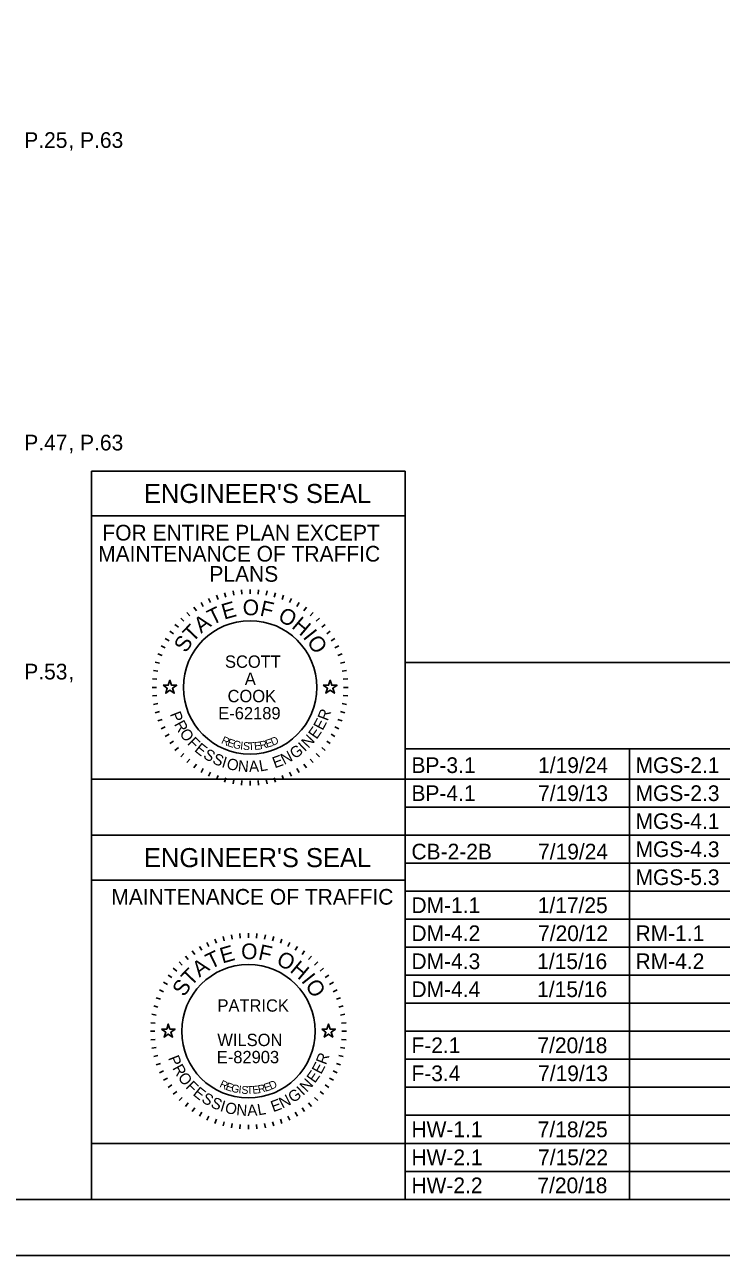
# Model space of a CAD drawing. Extents: x 0 to 34, y -32.5 to 22.
# Drawn here: x 6.75 to 12.97, y 0 to 10.98 of the extents above; entities that cross this region are included whole.
import ezdxf

# ---------------------------------------------------------------- set-up
doc = ezdxf.new("R2010")
doc.units = 0
for name, color, linetype in [('Default', 7, 'Continuous'), ('GM_X_Adjacent_County', 7, 'Continuous'), ('GM_X_County', 7, 'Continuous'), ('GM_X_Section', 7, 'Continuous'), ('GM_X_Township', 7, 'Continuous')]:
    doc.layers.add(name, color=color, linetype=linetype)

msp = doc.modelspace()

# ---------------------------------------------------------------- linework, layer by layer
at = {"layer": 'Default'}
for points in [[(7.988, 5.089), (8.035, 5.089), (8.05, 5.133), (8.064, 5.089), (8.111, 5.089), (8.073, 5.061), (8.088, 5.017), (8.05, 5.044), (8.012, 5.017), (8.026, 5.061)], [(9.418, 5.089), (9.465, 5.089), (9.48, 5.133), (9.494, 5.089), (9.541, 5.089), (9.503, 5.061), (9.518, 5.017), (9.48, 5.044), (9.442, 5.017), (9.456, 5.061)], [(7.974, 2.02), (8.021, 2.02), (8.035, 2.065), (8.049, 2.02), (8.096, 2.02), (8.058, 1.992), (8.073, 1.948), (8.035, 1.975), (7.997, 1.948), (8.012, 1.992)], [(9.404, 2.02), (9.451, 2.02), (9.465, 2.065), (9.479, 2.02), (9.526, 2.02), (9.488, 1.992), (9.503, 1.948), (9.465, 1.975), (9.427, 1.948), (9.442, 1.992)]]:
    msp.add_lwpolyline(points, close=True, dxfattribs=at)
at = {"layer": 'GM_X_County'}
msp.add_lwpolyline([(1.5, 21.5), (33.5, 21.5), (33.5, 0.5), (1.5, 0.5)], close=True, dxfattribs=at)
at = {"layer": 'GM_X_Section'}
msp.add_lwpolyline([(0, 0), (34, 0), (34, 22), (0, 22)], close=True, dxfattribs=at)
at = {"layer": 'GM_X_Township'}
for p, q in [((7.35, 3.75), (7.35, 7)), ((7.35, 7), (10.15, 7)), ((10.15, 7), (10.15, 3.75)), ((7.35, 6.6), (10.15, 6.6)), ((8.688, 5.941), (8.692, 5.901)), ((8.765, 5.944), (8.765, 5.904)), ((8.841, 5.941), (8.837, 5.901)), ((8.327, 5.827), (8.347, 5.792)), ((8.395, 5.862), (8.412, 5.826)), ((8.465, 5.891), (8.479, 5.854)), ((8.538, 5.914), (8.549, 5.875)), ((8.613, 5.931), (8.62, 5.891)), ((8.917, 5.931), (8.91, 5.891)), ((8.991, 5.914), (8.981, 5.875)), ((9.064, 5.891), (9.05, 5.854)), ((9.134, 5.862), (9.118, 5.826)), ((9.202, 5.827), (9.182, 5.792)), ((8.202, 5.739), (8.228, 5.709)), ((8.263, 5.786), (8.286, 5.753)), ((9.267, 5.786), (9.244, 5.753)), ((9.327, 5.739), (9.301, 5.709)), ((8.094, 5.631), (8.125, 5.606)), ((8.146, 5.688), (8.174, 5.659)), ((9.383, 5.688), (9.355, 5.659)), ((9.435, 5.631), (9.404, 5.606)), ((8.007, 5.506), (8.042, 5.486)), ((8.048, 5.571), (8.081, 5.548)), ((9.481, 5.571), (9.449, 5.548)), ((9.522, 5.506), (9.488, 5.486)), ((7.972, 5.439), (8.008, 5.422)), ((9.558, 5.439), (9.521, 5.422)), ((7.919, 5.295), (7.958, 5.285)), ((7.942, 5.368), (7.98, 5.355)), ((9.587, 5.368), (9.549, 5.355)), ((9.61, 5.295), (9.571, 5.285)), ((10.15, 5.292), (23.6, 5.292)), ((10.15, 0.5), (10.15, 5.292)), ((7.903, 5.221), (7.942, 5.214)), ((9.626, 5.221), (9.587, 5.214)), ((7.89, 5.069), (7.93, 5.069)), ((7.893, 5.145), (7.933, 5.142)), ((9.636, 5.145), (9.596, 5.142)), ((9.64, 5.069), (9.6, 5.069)), ((7.893, 4.993), (7.933, 4.996)), ((9.636, 4.993), (9.596, 4.996)), ((7.903, 4.917), (7.942, 4.924)), ((7.919, 4.842), (7.958, 4.853)), ((9.61, 4.842), (9.571, 4.853)), ((9.626, 4.917), (9.587, 4.924)), ((7.942, 4.77), (7.98, 4.783)), ((9.587, 4.77), (9.549, 4.783)), ((7.972, 4.699), (8.008, 4.716)), ((8.007, 4.631), (8.042, 4.651)), ((9.522, 4.631), (9.488, 4.651)), ((9.558, 4.699), (9.521, 4.716)), ((8.048, 4.567), (8.081, 4.59)), ((8.094, 4.506), (8.125, 4.532)), ((9.435, 4.506), (9.404, 4.532)), ((9.481, 4.567), (9.449, 4.59)), ((10.15, 4.521), (23.6, 4.521)), ((12.15, 0.5), (12.15, 4.521)), ((8.146, 4.45), (8.174, 4.478)), ((8.202, 4.399), (8.228, 4.429)), ((9.327, 4.399), (9.301, 4.429)), ((9.383, 4.45), (9.355, 4.478)), ((8.263, 4.352), (8.286, 4.385)), ((8.327, 4.311), (8.347, 4.346)), ((8.395, 4.276), (8.412, 4.312)), ((8.465, 4.247), (8.479, 4.284)), ((9.064, 4.247), (9.05, 4.284)), ((9.134, 4.276), (9.118, 4.312)), ((9.202, 4.311), (9.182, 4.346)), ((9.267, 4.352), (9.244, 4.385)), ((8.538, 4.224), (8.549, 4.262)), ((8.613, 4.207), (8.62, 4.247)), ((8.688, 4.197), (8.692, 4.237)), ((8.765, 4.194), (8.765, 4.234)), ((8.841, 4.197), (8.837, 4.237)), ((8.917, 4.207), (8.91, 4.247)), ((8.991, 4.224), (8.981, 4.262)), ((10.15, 4.25), (23.6, 4.25)), ((10.15, 4), (23.6, 4)), ((7.35, 3.75), (10.15, 3.75)), ((7.35, 0.5), (7.35, 3.75)), ((7.35, 3.75), (10.15, 3.75)), ((10.15, 3.75), (23.6, 3.75)), ((10.15, 3.75), (10.15, 0.5)), ((10.15, 3.75), (10.15, 0.5)), ((10.15, 3.5), (23.6, 3.5)), ((7.35, 3.35), (10.15, 3.35)), ((10.15, 3.25), (23.6, 3.25)), ((10.15, 3), (23.6, 3)), ((8.598, 2.862), (8.605, 2.822)), ((8.674, 2.872), (8.677, 2.832)), ((8.75, 2.875), (8.75, 2.835)), ((8.826, 2.872), (8.823, 2.832)), ((8.902, 2.862), (8.895, 2.822)), ((8.313, 2.758), (8.333, 2.723)), ((8.38, 2.793), (8.397, 2.757)), ((8.451, 2.822), (8.464, 2.785)), ((8.524, 2.845), (8.534, 2.807)), ((8.976, 2.845), (8.966, 2.807)), ((9.049, 2.822), (9.036, 2.785)), ((9.12, 2.793), (9.103, 2.757)), ((9.187, 2.758), (9.167, 2.723)), ((10.15, 2.75), (23.6, 2.75)), ((8.188, 2.67), (8.213, 2.64)), ((8.248, 2.717), (8.271, 2.684)), ((9.252, 2.717), (9.229, 2.684)), ((9.312, 2.67), (9.287, 2.64)), ((8.08, 2.562), (8.11, 2.537)), ((8.131, 2.619), (8.16, 2.59)), ((9.369, 2.619), (9.34, 2.59)), ((9.42, 2.562), (9.39, 2.537)), ((7.992, 2.438), (8.027, 2.418)), ((8.033, 2.502), (8.066, 2.479)), ((9.467, 2.502), (9.434, 2.479)), ((9.508, 2.438), (9.473, 2.418)), ((10.15, 2.5), (23.6, 2.5)), ((7.957, 2.37), (7.993, 2.353)), ((9.543, 2.37), (9.507, 2.353)), ((7.905, 2.226), (7.943, 2.216)), ((7.928, 2.299), (7.965, 2.286)), ((9.572, 2.299), (9.535, 2.286)), ((9.595, 2.226), (9.557, 2.216)), ((10.15, 2.25), (23.6, 2.25)), ((7.888, 2.152), (7.928, 2.145)), ((9.612, 2.152), (9.572, 2.145)), ((7.875, 2), (7.915, 2)), ((7.878, 2.076), (7.918, 2.073)), ((9.622, 2.076), (9.582, 2.073)), ((9.625, 2), (9.585, 2)), ((10.15, 2), (23.6, 2)), ((7.878, 1.924), (7.918, 1.927)), ((9.622, 1.924), (9.582, 1.927)), ((7.888, 1.848), (7.928, 1.855)), ((7.905, 1.774), (7.943, 1.784)), ((9.595, 1.774), (9.557, 1.784)), ((9.612, 1.848), (9.572, 1.855)), ((7.928, 1.701), (7.965, 1.714)), ((9.572, 1.701), (9.535, 1.714)), ((10.15, 1.75), (23.6, 1.75)), ((7.957, 1.63), (7.993, 1.647)), ((7.992, 1.563), (8.027, 1.583)), ((9.508, 1.563), (9.473, 1.583)), ((9.543, 1.63), (9.507, 1.647)), ((8.033, 1.498), (8.066, 1.521)), ((8.08, 1.438), (8.11, 1.463)), ((9.42, 1.438), (9.39, 1.463)), ((9.467, 1.498), (9.434, 1.521)), ((10.15, 1.5), (23.6, 1.5)), ((8.131, 1.381), (8.16, 1.41)), ((8.188, 1.33), (8.213, 1.36)), ((9.312, 1.33), (9.287, 1.36)), ((9.369, 1.381), (9.34, 1.41)), ((8.248, 1.283), (8.271, 1.316)), ((8.313, 1.242), (8.333, 1.277)), ((8.38, 1.207), (8.397, 1.243)), ((8.451, 1.178), (8.464, 1.215)), ((9.049, 1.178), (9.036, 1.215)), ((9.12, 1.207), (9.103, 1.243)), ((9.187, 1.242), (9.167, 1.277)), ((9.252, 1.283), (9.229, 1.316)), ((10.15, 1.25), (23.6, 1.25)), ((8.524, 1.155), (8.534, 1.193)), ((8.598, 1.138), (8.605, 1.178)), ((8.674, 1.128), (8.677, 1.168)), ((8.75, 1.125), (8.75, 1.165)), ((8.826, 1.128), (8.823, 1.168)), ((8.902, 1.138), (8.895, 1.178)), ((8.976, 1.155), (8.966, 1.193)), ((10.15, 1), (23.6, 1)), ((10.15, 0.75), (23.6, 0.75)), ((7.35, 0.5), (10.15, 0.5)), ((7.35, 0.5), (10.15, 0.5))]:
    msp.add_line(p, q, dxfattribs=at)
for points in [[(7.35, 3.75), (7.35, 4.25), (10.15, 4.25), (10.15, 3.75)], [(7.35, 0.5), (7.35, 1), (10.15, 1), (10.15, 0.5)]]:
    msp.add_lwpolyline(points, close=True, dxfattribs=at)
for centre in [(8.765, 5.069), (8.75, 2)]:
    msp.add_circle(centre, 0.595, dxfattribs=at)

# ---------------------------------------------------------------- texts
at = {"layer": 'GM_X_Adjacent_County'}
for s, p in [('P.25', (6.75, 9.884)), ('P.63', (7.248, 9.884)), (', ', (7.143, 9.884)), ('P.47', (6.75, 7.184)), ('P.63', (7.248, 7.184)), (', ', (7.143, 7.184)), ('P.53', (6.75, 5.14)), (', ', (7.143, 5.14)), ('BP-3.1', (10.205, 4.305)), ('1/19/24', (11.335, 4.305)), ('MGS-2.1', (12.205, 4.305)), ('BP-4.1', (10.205, 4.055)), ('7/19/13', (11.335, 4.055)), ('MGS-2.3', (12.205, 4.055)), ('MGS-4.1', (12.205, 3.805)), ('CB-2-2B', (10.205, 3.534)), ('7/19/24', (11.335, 3.534)), ('MGS-4.3', (12.205, 3.555)), ('MGS-5.3', (12.205, 3.305)), ('DM-1.1', (10.205, 3.055)), ('1/17/25', (11.332, 3.055)), ('DM-4.2', (10.205, 2.805)), ('7/20/12', (11.335, 2.805)), ('RM-1.1', (12.205, 2.805)), ('DM-4.3', (10.205, 2.555)), ('1/15/16', (11.327, 2.555)), ('RM-4.2', (12.205, 2.555)), ('DM-4.4', (10.205, 2.305)), ('1/15/16', (11.327, 2.305)), ('F-2.1', (10.205, 1.805)), ('7/20/18', (11.329, 1.805)), ('F-3.4', (10.205, 1.555)), ('7/19/13', (11.335, 1.555)), ('HW-1.1', (10.205, 1.055)), ('7/18/25', (11.332, 1.055)), ('HW-2.1', (10.205, 0.805)), ('7/15/22', (11.335, 0.805)), ('HW-2.2', (10.205, 0.555)), ('7/20/18', (11.329, 0.555))]:
    msp.add_text(s, height=0.14, dxfattribs=at).set_placement(p)
at = {"layer": 'GM_X_Township'}
for s, height, p in [("ENGINEER'S SEAL", 0.17, (7.818, 6.715)), ('FOR ENTIRE PLAN EXCEPT', 0.14, (7.447, 6.38)), ('MAINTENANCE OF TRAFFIC', 0.14, (7.409, 6.192)), ('PLANS', 0.14, (8.402, 6.012)), ('SCOTT', 0.11, (8.541, 5.244)), ('A', 0.11, (8.718, 5.091)), ('COOK', 0.11, (8.564, 4.937)), ('E-62189', 0.11, (8.481, 4.784)), ("ENGINEER'S SEAL", 0.17, (7.818, 3.465)), ('MAINTENANCE OF TRAFFIC', 0.14, (7.527, 3.13)), ('PATRICK', 0.11, (8.474, 2.175)), ('WILSON', 0.11, (8.473, 1.868)), ('E-82903', 0.11, (8.468, 1.715))]:
    msp.add_text(s, height=height, dxfattribs=at).set_placement(p)
for s, height, rotation, p in [('E', 0.14, 15.7571, (8.533, 5.673)), ('O', 0.14, 359.7812, (8.699, 5.713)), ('F', 0.14, 347.4362, (8.846, 5.711)), ('T', 0.14, 25.7167, (8.426, 5.621)), ('O', 0.14, 332.2586, (9.004, 5.67)), ('T', 0.14, 46.4344, (8.253, 5.465)), ('A', 0.14, 36.4747, (8.328, 5.547)), ('H', 0.14, 319.9136, (9.128, 5.605)), ('S', 0.14, 57.1924, (8.193, 5.37)), ('I', 0.14, 308.367, (9.231, 5.517)), ('O', 0.14, 303.1491, (9.267, 5.478)), ('P', 0.1, 291.494, (8.047, 4.831)), ('R', 0.1, 69.2322, (9.457, 4.764)), ('R', 0.1, 298.7311, (8.084, 4.741)), ('E', 0.1, 54.758, (9.358, 4.6)), ('E', 0.1, 61.9951, (9.412, 4.679)), ('O', 0.1, 306.4666, (8.13, 4.657)), ('F', 0.1, 314.7068, (8.199, 4.567)), ('R', 0.07, 334.487, (8.502, 4.574)), ('D', 0.07, 23.3052, (8.966, 4.546)), ('N', 0.1, 47.0224, (9.285, 4.52)), ('E', 0.1, 321.4393, (8.262, 4.504)), ('S', 0.1, 328.6764, (8.339, 4.444)), ('E', 0.07, 341.04, (8.555, 4.549)), ('G', 0.07, 347.4752, (8.606, 4.531)), ('I', 0.07, 353.7858, (8.674, 4.516)), ('S', 0.07, 356.8926, (8.7, 4.512)), ('T', 0.07, 3.0061, (8.75, 4.508)), ('E', 0.07, 6.0117, (8.804, 4.51)), ('R', 0.07, 11.9184, (8.857, 4.516)), ('E', 0.07, 17.6836, (8.914, 4.529)), ('N', 0.1, 27.3113, (9.069, 4.376)), ('G', 0.1, 35.0469, (9.163, 4.426)), ('I', 0.1, 43.287, (9.252, 4.49)), ('S', 0.1, 335.9134, (8.421, 4.396)), ('I', 0.1, 343.1505, (8.505, 4.359)), ('O', 0.1, 346.8859, (8.549, 4.344)), ('N', 0.1, 355.1261, (8.653, 4.321)), ('A', 0.1, 2.8617, (8.757, 4.313)), ('L', 0.1, 10.0987, (8.854, 4.318)), ('E', 0.1, 20.0742, (8.986, 4.346)), ('E', 0.14, 15.7571, (8.518, 2.604)), ('O', 0.14, 359.7812, (8.685, 2.644)), ('F', 0.14, 347.4362, (8.831, 2.642)), ('T', 0.14, 25.7167, (8.412, 2.552)), ('O', 0.14, 332.2586, (8.99, 2.602)), ('T', 0.14, 46.4344, (8.238, 2.396)), ('A', 0.14, 36.4747, (8.313, 2.478)), ('H', 0.14, 319.9136, (9.113, 2.536)), ('S', 0.14, 57.1924, (8.178, 2.301)), ('I', 0.14, 308.367, (9.216, 2.448)), ('O', 0.14, 303.1491, (9.252, 2.409)), ('P', 0.1, 291.494, (8.032, 1.762)), ('R', 0.1, 69.2322, (9.442, 1.695)), ('R', 0.1, 298.7311, (8.069, 1.672)), ('E', 0.1, 54.758, (9.343, 1.531)), ('E', 0.1, 61.9951, (9.398, 1.61)), ('O', 0.1, 306.4666, (8.115, 1.588)), ('F', 0.1, 314.7068, (8.184, 1.498)), ('R', 0.07, 334.487, (8.487, 1.505)), ('E', 0.07, 341.04, (8.541, 1.48)), ('E', 0.07, 17.6836, (8.9, 1.46)), ('D', 0.07, 23.3052, (8.951, 1.477)), ('N', 0.1, 47.0224, (9.27, 1.451)), ('E', 0.1, 321.4393, (8.248, 1.435)), ('S', 0.1, 328.6764, (8.324, 1.375)), ('G', 0.07, 347.4752, (8.591, 1.462)), ('I', 0.07, 353.7858, (8.659, 1.447)), ('S', 0.07, 356.8926, (8.686, 1.443)), ('T', 0.07, 3.0061, (8.736, 1.439)), ('E', 0.07, 6.0117, (8.789, 1.441)), ('R', 0.07, 11.9184, (8.842, 1.447)), ('N', 0.1, 27.3113, (9.054, 1.308)), ('G', 0.1, 35.0469, (9.148, 1.357)), ('I', 0.1, 43.287, (9.237, 1.421)), ('S', 0.1, 335.9134, (8.406, 1.327)), ('I', 0.1, 343.1505, (8.491, 1.29)), ('O', 0.1, 346.8859, (8.534, 1.275)), ('N', 0.1, 355.1261, (8.639, 1.252)), ('A', 0.1, 2.8617, (8.742, 1.244)), ('L', 0.1, 10.0987, (8.839, 1.249)), ('E', 0.1, 20.0742, (8.971, 1.277))]:
    msp.add_text(s, height=height, rotation=rotation, dxfattribs=at).set_placement(p)

doc.saveas('drawing.dxf')
